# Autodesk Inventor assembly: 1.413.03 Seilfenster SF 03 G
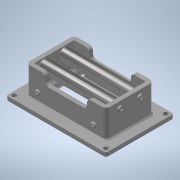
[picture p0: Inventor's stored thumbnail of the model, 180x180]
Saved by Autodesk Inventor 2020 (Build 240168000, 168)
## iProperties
Created: 2016-10
Part Number: 1.413.03 Seilfenster SF 03 G
Document SubType Name: Assembly
Designer: C.Perkuhn
Mass: 3593.9 g
Surface Area: 3471.09 cm^2
Volume: 1015.97 cm^3
Density: 3.5374 g/cm^3
Project: SF 03 G
Description: Seilfenster SF 03 G
Stock Number: 1.413.03
Author: C.Perkuhn
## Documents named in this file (8)
- Z:\Workspace\03 Seilrollen\1.413 Seilfenster\1.413.03 Seilfenster SF 03 G\1.413.03 Seilfenster SF 03 G.iam
- Z:\Workspace\03 Seilrollen\1.413 Seilfenster\Lagerbuchsen\bb202425bp25__.ipt
- Z:\Workspace\03 Seilrollen\de-DE\ISO 7380\ISO 7380 - M8 x 25.ipt
- Z:\Workspace\03 Seilrollen\1.413 Seilfenster\1.413.03 Seilfenster SF 03 G\1.413.03.01 Konsole Schweißteil.iam
- Z:\Workspace\03 Seilrollen\1.413 Seilfenster\1.413.03 Seilfenster SF 03 G\1.413.03.05 Achse kurz.ipt
- Z:\Workspace\03 Seilrollen\1.413 Seilfenster\1.413.03 Seilfenster SF 03 G\1.413.03.04 Rohr ø30 x 3,5.ipt
- Z:\Workspace\03 Seilrollen\1.413 Seilfenster\1.413.03 Seilfenster SF 03 G\1.413.03.06 Rohr ø30 x 3,5 lang.ipt
- Z:\Workspace\03 Seilrollen\1.413 Seilfenster\1.413.03 Seilfenster SF 03 G\1.413.03.07 Achse lang.ipt
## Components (25 placed, 7 different names)
1. 1.413.03.01 Konsole Schweißteil:1 [sub-assembly] — Einfügen:7, Einfügen:8, Einfügen:15, Einfügen:16, Einfügen:26, Einfügen:27, Einfügen:28, Einfügen:29, Einfügen:30, Einfügen:31, Einfügen:32, Einfügen:33
2. 1.413.03.05 Achse kurz:1 — Einfügen:7
3. 1.413.03.05 Achse kurz:2 — Einfügen:8
4. 1.413.03.04 Rohr ø30 x 3,5:1 — Einfügen:1, Einfügen:3
5. 1.413.03.04 Rohr ø30 x 3,5:2 — Einfügen:2, Einfügen:4
6. bb202425bp25__:1 — Einfügen:1
7. bb202425bp25__:2 — Einfügen:2
8. bb202425bp25__:3 — Einfügen:3
9. bb202425bp25__:4 — Einfügen:4
10. bb202425bp25__:5 — Einfügen:36
11. bb202425bp25__:6 — Einfügen:34
12. bb202425bp25__:7 — Einfügen:35
13. bb202425bp25__:8 — Einfügen:25, Einfügen:37
14. 1.413.03.07 Achse lang:1 — Einfügen:16, Einfügen:25
15. 1.413.03.07 Achse lang:2 — Einfügen:15
16. ISO 7380 M8 x 25:1 — Einfügen:26
17. ISO 7380 M8 x 25:2 — Einfügen:27
18. ISO 7380 M8 x 25:3 — Einfügen:28
19. ISO 7380 M8 x 25:4 — Einfügen:29
20. ISO 7380 M8 x 25:5 — Einfügen:30
21. ISO 7380 M8 x 25:6 — Einfügen:33
22. ISO 7380 M8 x 25:7 — Einfügen:32
23. ISO 7380 M8 x 25:8 — Einfügen:31
24. 1.413.03.06 Rohr ø30 x 3,5 lang:3 — Einfügen:34, Einfügen:36
25. 1.413.03.06 Rohr ø30 x 3,5 lang:4 — Einfügen:35, Einfügen:37
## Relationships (21: Insert 21)
- Einfügen:1 [Insert]: 1.413.03.04 Rohr ø30 x 3,5:1 ↔ bb202425bp25__:1
- Einfügen:2 [Insert]: 1.413.03.04 Rohr ø30 x 3,5:2 ↔ bb202425bp25__:2
- Einfügen:3 [Insert]: 1.413.03.04 Rohr ø30 x 3,5:1 ↔ bb202425bp25__:3
- Einfügen:4 [Insert]: 1.413.03.04 Rohr ø30 x 3,5:2 ↔ bb202425bp25__:4
- Einfügen:7 [Insert]: 1.413.03.01 Konsole Schweißteil:1 ↔ 1.413.03.05 Achse kurz:1
- Einfügen:8 [Insert]: 1.413.03.01 Konsole Schweißteil:1 ↔ 1.413.03.05 Achse kurz:2
- Einfügen:15 [Insert]: 1.413.03.01 Konsole Schweißteil:1 ↔ 1.413.03.07 Achse lang:2
- Einfügen:16 [Insert]: 1.413.03.01 Konsole Schweißteil:1 ↔ 1.413.03.07 Achse lang:1
- Einfügen:25 [Insert]: bb202425bp25__:8 ↔ 1.413.03.07 Achse lang:1
- Einfügen:26 [Insert]: 1.413.03.01 Konsole Schweißteil:1 ↔ ISO 7380 M8 x 25:1
- Einfügen:27 [Insert]: 1.413.03.01 Konsole Schweißteil:1 ↔ ISO 7380 M8 x 25:2
- Einfügen:28 [Insert]: 1.413.03.01 Konsole Schweißteil:1 ↔ ISO 7380 M8 x 25:3
- Einfügen:29 [Insert]: 1.413.03.01 Konsole Schweißteil:1 ↔ ISO 7380 M8 x 25:4
- Einfügen:30 [Insert]: 1.413.03.01 Konsole Schweißteil:1 ↔ ISO 7380 M8 x 25:5
- Einfügen:31 [Insert]: 1.413.03.01 Konsole Schweißteil:1 ↔ ISO 7380 M8 x 25:8
- Einfügen:32 [Insert]: 1.413.03.01 Konsole Schweißteil:1 ↔ ISO 7380 M8 x 25:7
- Einfügen:33 [Insert]: 1.413.03.01 Konsole Schweißteil:1 ↔ ISO 7380 M8 x 25:6
- Einfügen:34 [Insert]: bb202425bp25__:6 ↔ 1.413.03.06 Rohr ø30 x 3,5 lang:3
- Einfügen:35 [Insert]: bb202425bp25__:7 ↔ 1.413.03.06 Rohr ø30 x 3,5 lang:4
- Einfügen:36 [Insert]: bb202425bp25__:5 ↔ 1.413.03.06 Rohr ø30 x 3,5 lang:3
- Einfügen:37 [Insert]: bb202425bp25__:8 ↔ 1.413.03.06 Rohr ø30 x 3,5 lang:4
